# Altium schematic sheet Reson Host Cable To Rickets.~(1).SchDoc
size Tabloid; Organization: Monterey Bay Aquarium Research Institute; Address1: 7700 Sandholdt Rd; Address2: Moss Landing, CA 95039-9644; CompanyName: MBARI
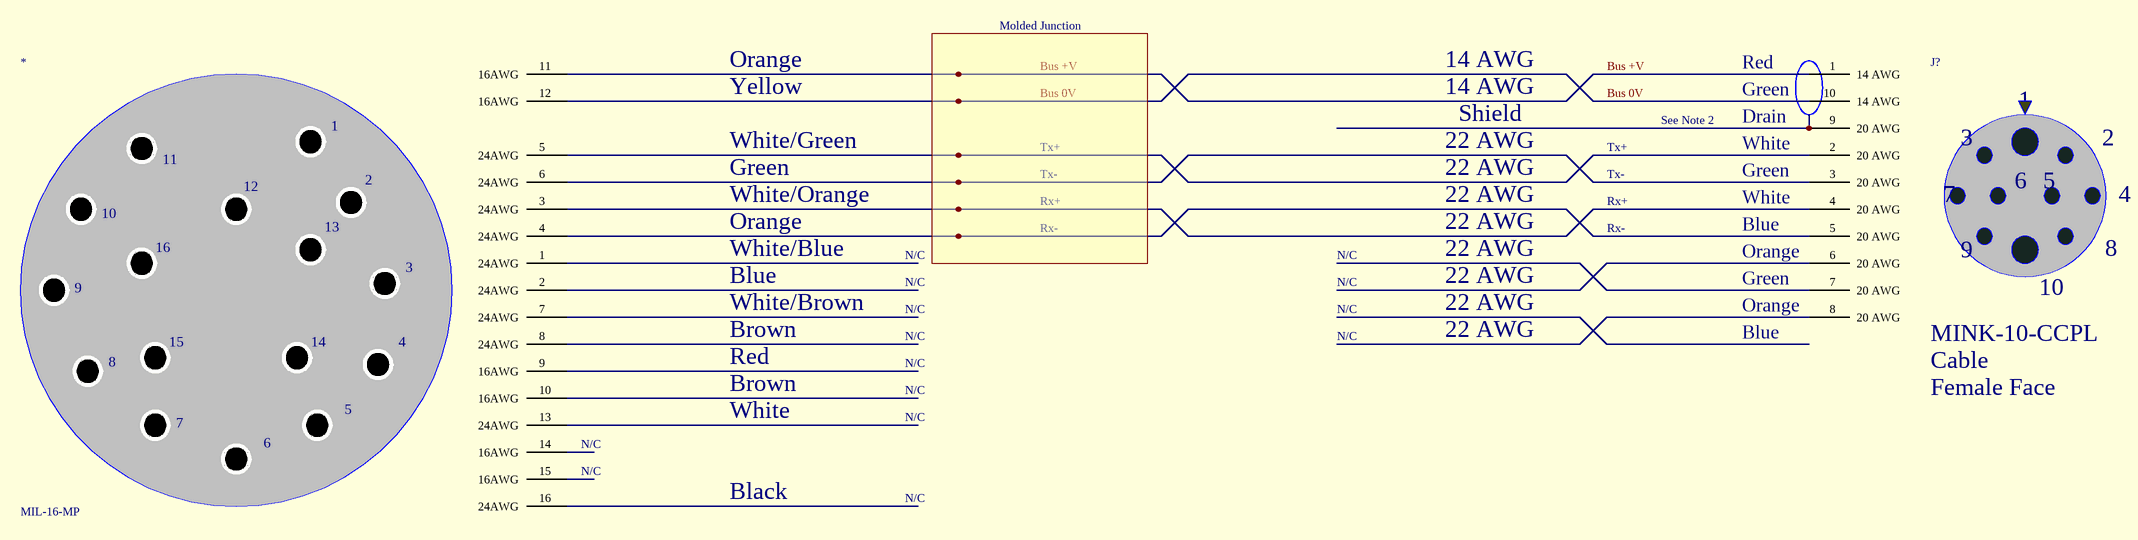
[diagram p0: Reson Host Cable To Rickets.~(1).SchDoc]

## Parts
*  MIL-16-MP
J?  MINK-10-CCPL  DescSheet: Cable  View: Female Face

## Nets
Bus 0V: *.12(16AWG) J?.10(14_AWG)
Bus +V: *.11(16AWG) J?.1(14_AWG)
Net*_3: *.3(24AWG) J?.4(20_AWG)
Net*_4: *.4(24AWG) J?.5(20_AWG)
Net*_5: *.5(24AWG) J?.2(20_AWG)
Net*_6: *.6(24AWG) J?.3(20_AWG)

Not connected (* = marked no-connect by the designer): * 1(24AWG) 2(24AWG) 7(24AWG) 8(24AWG) 9(16AWG) 10(16AWG) 13(24AWG) 14(16AWG) 15(16AWG) 16(24AWG); J? 6(20_AWG) 7(20_AWG) 8(20_AWG) 9(20_AWG)

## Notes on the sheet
- Molded Junction
- Orange
- Yellow
- 14 AWG
- Shield
- See Note 2
- Red
- Green
- Drain
- White/Green
- Tx+
- Tx-
- 22 AWG
- White
- White/Blue
- White/Orange
- N/C
- Rx+
- Rx-
- Blue
- (near J?) Orange
- White/Brown
- Brown
- Black

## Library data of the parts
J? = SEACON-MINK-10-CCP-SOC: Seacon MINK-10/L-CCP Connector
